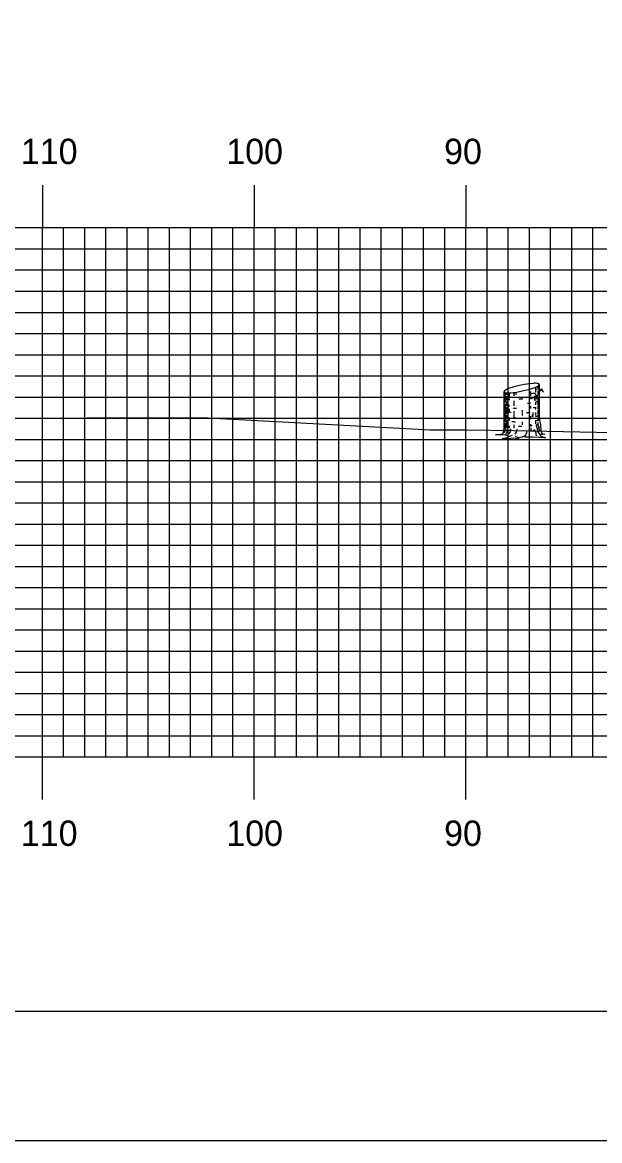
# Model space of a CAD drawing. Extents: x 1771235 to 1771579, y 442591 to 442811.
# Drawn here: x 1771290.1 to 1771317.4, y 442590.5 to 442643.4 of the extents above; entities that cross this region are included whole.
import ezdxf

# ---------------------------------------------------------------- set-up
doc = ezdxf.new("R2010")
doc.units = 0
for name, color, linetype in [('BORDER', 7, 'Continuous'), ('H_V ANNOTATION', 7, 'Continuous'), ('M_Trees_Conifer_Pay', 7, 'Continuous'), ('MAJOR', 7, 'Continuous'), ('MINOR', 7, 'Continuous'), ('PLOT BOUNDARY', 7, 'Continuous'), ('S_Roadway_Centerline', 7, 'Continuous')]:
    doc.layers.add(name, color=color, linetype=linetype)

msp = doc.modelspace()

# ---------------------------------------------------------------- linework, layer by layer
at = {"layer": 'BORDER'}
msp.add_lwpolyline([(1771251.467, 442596.665), (1771571.467, 442596.665), (1771571.467, 442806.665), (1771251.467, 442806.665)], close=True, dxfattribs=at)
at = {"layer": 'M_Trees_Conifer_Pay'}
for p, q in [((1771314.538, 442624.609), (1771314.538, 442626.256)), ((1771312.874, 442624.199), (1771312.874, 442625.921)), ((1771312.921, 442625.884), (1771312.921, 442625.412)), ((1771312.979, 442625.872), (1771312.979, 442625.775)), ((1771312.979, 442625.7), (1771312.979, 442625.496)), ((1771313.105, 442625.864), (1771313.105, 442625.632)), ((1771313.325, 442625.885), (1771313.325, 442625.717)), ((1771314.12, 442625.927), (1771314.12, 442625.727)), ((1771314.349, 442626.123), (1771314.349, 442625.9)), ((1771314.349, 442625.811), (1771314.349, 442625.764)), ((1771314.466, 442626.184), (1771314.466, 442626.021)), ((1771314.466, 442625.954), (1771314.466, 442625.826)), ((1771312.921, 442625.348), (1771312.921, 442625.04)), ((1771312.979, 442625.439), (1771312.979, 442625.239)), ((1771312.979, 442625.192), (1771312.979, 442624.856)), ((1771313.105, 442625.592), (1771313.105, 442625.517)), ((1771313.325, 442625.48), (1771313.325, 442625.243)), ((1771313.73, 442625.653), (1771313.73, 442625.558)), ((1771314.12, 442625.67), (1771314.12, 442625.581)), ((1771314.12, 442625.233), (1771314.12, 442625.128)), ((1771314.349, 442625.429), (1771314.349, 442625.297)), ((1771314.349, 442625.186), (1771314.349, 442625.076)), ((1771314.406, 442625.628), (1771314.355, 442625.569)), ((1771314.466, 442625.639), (1771314.466, 442625.303)), ((1771314.466, 442625.266), (1771314.466, 442625.103)), ((1771312.921, 442624.992), (1771312.921, 442624.5)), ((1771312.979, 442624.803), (1771312.979, 442624.667)), ((1771313.105, 442625.114), (1771313.105, 442624.975)), ((1771313.105, 442624.704), (1771313.105, 442624.562)), ((1771313.325, 442624.998), (1771313.325, 442624.846)), ((1771313.325, 442624.803), (1771313.325, 442624.63)), ((1771313.73, 442625.04), (1771313.73, 442624.966)), ((1771313.73, 442624.941), (1771313.73, 442624.792)), ((1771314.12, 442624.761), (1771314.12, 442624.615)), ((1771314.349, 442624.941), (1771314.349, 442624.799)), ((1771314.466, 442625.056), (1771314.466, 442624.84)), ((1771314.466, 442624.809), (1771314.466, 442624.735)), ((1771314.466, 442624.694), (1771314.466, 442624.521)), ((1771312.921, 442624.447), (1771312.921, 442624.199)), ((1771312.979, 442624.568), (1771312.979, 442624.189)), ((1771313.105, 442624.3), (1771313.105, 442624.206)), ((1771313.325, 442624.352), (1771313.325, 442624.199)), ((1771313.73, 442624.5), (1771313.73, 442624.347)), ((1771314.12, 442624.383), (1771314.12, 442624.294)), ((1771314.349, 442624.572), (1771314.349, 442624.399)), ((1771313.105, 442623.806), (1771313.267, 442623.87)), ((1771313.542, 442623.742), (1771313.416, 442623.806))]:
    msp.add_line(p, q, dxfattribs=at)
for points in [[(1771314.321, 442625.717), (1771314.29, 442625.632), (1771314.286, 442625.565), (1771314.317, 442625.501)], [(1771314.355, 442625.754), (1771314.391, 442625.68), (1771314.439, 442625.737), (1771314.496, 442625.805), (1771314.589, 442625.999), (1771314.653, 442626.046), (1771314.684, 442626.053)], [(1771314.369, 442625.501), (1771314.406, 442625.628), (1771314.47, 442625.744), (1771314.5, 442625.811), (1771314.569, 442625.958)], [(1771314.584, 442625.987), (1771314.659, 442625.995), (1771314.731, 442625.896)], [(1771313.053, 442625.227), (1771313.047, 442625.322), (1771313.09, 442625.299), (1771313.09, 442625.204)], [(1771314.192, 442624.828), (1771314.204, 442624.751), (1771314.252, 442624.761), (1771314.239, 442624.928)], [(1771314.538, 442624.609), (1771314.589, 442624.347), (1771314.605, 442624.074), (1771314.663, 442623.948), (1771314.799, 442623.918), (1771314.569, 442623.88), (1771314.569, 442623.88), (1771314.575, 442623.833), (1771314.822, 442623.738), (1771314.548, 442623.755), (1771314.192, 442623.775), (1771313.87, 442623.765), (1771313.877, 442623.847), (1771313.729, 442623.765), (1771313.542, 442623.742), (1771313.566, 442623.674), (1771313.298, 442623.718), (1771313.078, 442623.691), (1771312.785, 442623.708), (1771313.074, 442623.765), (1771313.105, 442623.806), (1771312.942, 442623.864), (1771312.705, 442623.874), (1771312.464, 442623.874), (1771312.806, 442623.932), (1771312.847, 442624.012), (1771312.874, 442624.199)], [(1771312.922, 442624.152), (1771312.901, 442624.074), (1771312.88, 442623.979)], [(1771313, 442624.132), (1771313.006, 442624.016), (1771312.952, 442623.927), (1771312.942, 442623.864)], [(1771313.162, 442624.158), (1771313.162, 442624.027), (1771313.074, 442623.927)], [(1771313.389, 442623.918), (1771313.456, 442624.012), (1771313.483, 442624.152)], [(1771314.128, 442624.216), (1771314.138, 442624.09), (1771314.212, 442624.047)], [(1771314.365, 442624.321), (1771314.439, 442624.216), (1771314.443, 442624.043), (1771314.569, 442623.88)], [(1771314.464, 442624.467), (1771314.47, 442624.321), (1771314.517, 442624.253), (1771314.527, 442624.053)], [(1771313.877, 442623.847), (1771313.951, 442623.989), (1771313.961, 442624.09)], [(1771314.406, 442623.827), (1771314.391, 442623.965), (1771314.317, 442624.094)]]:
    msp.add_lwpolyline(points, dxfattribs=at)
for centre, radius, start, end in [((1771314.73, 442621.153), 5.179, 101.7194, 108.0594), ((1771314.73, 442621.153), 5.179, 95.3794, 101.7194), ((1771314.319, 442625.511), 0.802, 79.2194, 95.3794), ((1771314.422, 442626.053), 0.251, 71.0501, 79.2194), ((1771314.349, 442626.406), 0.251, 304.2194, 312.3887), ((1771314.477, 442626.212), 0.0817, 56.7194, 71.0501), ((1771314.463, 442626.282), 0.0817, 312.3887, 326.7194), ((1771314.493, 442626.237), 0.0527, 46.923, 56.7194), ((1771314.508, 442626.252), 0.0314, 34.2194, 46.923), ((1771314.487, 442626.266), 0.0527, 326.7194, 336.5158), ((1771314.512, 442626.255), 0.0264, 23.4074, 34.2194), ((1771314.507, 442626.257), 0.0314, 336.5158, 349.2194), ((1771314.515, 442626.256), 0.0226, 11.7194, 23.4074), ((1771314.515, 442626.256), 0.0226, 0.0315, 11.7194), ((1771314.511, 442626.256), 0.0264, 349.2194, 0.0315), ((1771312.906, 442625.743), 0.0334, 163.9485, 180), ((1771312.906, 442625.743), 0.0334, 180, 196.0515), ((1771312.905, 442625.92), 0.0314, 156.5158, 169.2194), ((1771312.9, 442625.921), 0.0264, 169.2194, 180.0315), ((1771312.896, 442625.921), 0.0226, 180.0315, 191.7194), ((1771312.896, 442625.921), 0.0226, 191.7194, 203.4074), ((1771312.916, 442625.746), 0.0441, 196.0515, 210), ((1771312.925, 442625.911), 0.0527, 146.7194, 156.5158), ((1771312.9, 442625.922), 0.0264, 203.4074, 214.2194), ((1771312.904, 442625.925), 0.0314, 214.2194, 226.923), ((1771312.932, 442625.755), 0.0624, 210, 228.7494), ((1771312.949, 442625.895), 0.0817, 132.3887, 146.7194), ((1771312.919, 442625.94), 0.0527, 226.923, 236.7194), ((1771312.935, 442625.965), 0.0817, 236.7194, 251.0501), ((1771313.004, 442625.837), 0.172, 228.7494, 240), ((1771313.063, 442625.771), 0.251, 124.2194, 132.3887), ((1771312.989, 442626.124), 0.251, 251.0501, 259.2194), ((1771313.204, 442626.182), 0.571, 240, 240.3367), ((1771313.373, 442625.315), 0.802, 108.0594, 124.2194), ((1771313.092, 442626.666), 0.802, 259.2194, 275.3794), ((1771312.682, 442631.024), 5.179, 275.3794, 281.7194), ((1771313.706, 442629.933), 4.124, 264.6955, 266.7331), ((1771312.682, 442631.024), 5.179, 281.7194, 288.0594), ((1771313.706, 442629.933), 4.124, 276.238, 278.1032), ((1771314.207, 442626.415), 0.571, 278.1032, 284.3667), ((1771314.039, 442626.862), 0.802, 288.0594, 304.2194), ((1771314.207, 442626.57), 0.571, 284.4317, 292.4132), ((1771314.207, 442626.415), 0.571, 297.0237, 300), ((1771314.406, 442626.225), 0.172, 300, 311.2506), ((1771314.406, 442626.07), 0.172, 300, 311.2506), ((1771314.479, 442626.142), 0.0624, 311.2506, 330), ((1771314.479, 442625.988), 0.0624, 311.2506, 330), ((1771314.494, 442626.133), 0.0441, 330, 343.9485), ((1771314.494, 442625.979), 0.0441, 330, 343.9485), ((1771314.505, 442626.13), 0.0334, 343.9485, 354.2151), ((1771314.505, 442625.976), 0.0334, 343.9485, 354.2151), ((1771312.906, 442625.296), 0.0334, 163.9485, 180), ((1771312.906, 442625.296), 0.0334, 180, 196.0515), ((1771312.916, 442625.299), 0.0441, 196.0515, 210), ((1771312.932, 442625.308), 0.0624, 210, 228.7494), ((1771313.004, 442625.391), 0.172, 228.7494, 240), ((1771313.204, 442625.736), 0.571, 240, 240.3367), ((1771313.205, 442625.971), 0.571, 240, 247.0587), ((1771313.204, 442626.182), 0.571, 246.8597, 257.9846), ((1771313.705, 442629.7), 4.124, 268.0751, 270), ((1771313.705, 442629.7), 4.124, 270, 270.3581), ((1771313.706, 442629.489), 4.124, 273.7052, 275.9504), ((1771313.705, 442629.7), 4.124, 275.7849, 277.0558), ((1771313.705, 442629.253), 4.124, 277.6125, 278.1032), ((1771314.205, 442625.736), 0.571, 278.1032, 286.9296), ((1771314.207, 442625.971), 0.571, 284.4493, 297.0429), ((1771314.205, 442625.736), 0.571, 297.1896, 300), ((1771314.405, 442625.391), 0.172, 300, 311.2506), ((1771314.477, 442625.308), 0.0624, 311.2506, 330), ((1771314.493, 442625.299), 0.0441, 330, 343.9485), ((1771314.503, 442625.296), 0.0334, 343.9485, 354.2151), ((1771314.504, 442625.532), 0.0334, 343.9485, 354.2151), ((1771312.906, 442625.086), 0.0334, 163.9485, 180), ((1771312.906, 442625.086), 0.0334, 180, 196.0515), ((1771312.906, 442624.849), 0.0334, 163.9485, 180), ((1771312.906, 442624.849), 0.0334, 180, 196.0515), ((1771312.906, 442624.651), 0.0334, 163.9485, 180), ((1771312.916, 442625.089), 0.0441, 196.0515, 210), ((1771312.916, 442624.852), 0.0441, 196.0515, 210), ((1771312.932, 442625.098), 0.0624, 210, 228.7494), ((1771312.932, 442624.861), 0.0624, 210, 228.7494), ((1771313.004, 442625.181), 0.172, 228.7494, 240), ((1771313.004, 442624.944), 0.172, 228.7494, 240), ((1771313.204, 442625.526), 0.571, 240, 246.8597), ((1771313.204, 442625.289), 0.571, 240, 246.8597), ((1771313.204, 442625.526), 0.571, 259.2707, 261.8968), ((1771313.705, 442629.043), 4.124, 261.8968, 263.1474), ((1771313.705, 442629.253), 4.124, 264.081, 266.6676), ((1771313.705, 442628.806), 4.124, 264.716, 266.3193), ((1771313.705, 442629.043), 4.124, 270, 270.3581), ((1771313.705, 442629.043), 4.124, 273.1493, 275.4569), ((1771314.205, 442625.289), 0.571, 285.3983, 297.1896), ((1771314.205, 442625.526), 0.571, 297.1896, 300), ((1771314.405, 442625.181), 0.172, 300, 311.2506), ((1771314.477, 442625.098), 0.0624, 311.2506, 330), ((1771314.477, 442624.664), 0.0624, 311.2506, 330), ((1771314.493, 442625.089), 0.0441, 330, 343.9485), ((1771314.493, 442624.654), 0.0441, 330, 343.9485), ((1771314.503, 442625.086), 0.0334, 343.9485, 354.2151), ((1771314.503, 442624.651), 0.0334, 343.9485, 354.2151), ((1771312.906, 442624.456), 0.0334, 163.9485, 180), ((1771312.906, 442624.456), 0.0334, 180, 196.0515), ((1771312.906, 442624.235), 0.0334, 163.9485, 180), ((1771312.906, 442624.235), 0.0334, 180, 196.0515), ((1771312.916, 442624.459), 0.0441, 196.0515, 210), ((1771312.916, 442624.238), 0.0441, 196.0515, 210), ((1771312.932, 442624.468), 0.0624, 210, 228.7494), ((1771312.932, 442624.248), 0.0624, 210, 228.7494), ((1771313.004, 442624.551), 0.172, 228.7494, 240), ((1771313.004, 442624.33), 0.172, 228.7494, 240), ((1771313.193, 442625.097), 0.571, 241.2369, 248.0268), ((1771313.204, 442624.896), 0.571, 240, 246.8597), ((1771313.204, 442624.675), 0.571, 240, 244.5314), ((1771313.705, 442628.193), 4.124, 262.4438, 263.512), ((1771313.705, 442628.609), 4.124, 263.4991, 265.8397), ((1771313.705, 442628.413), 4.124, 267.8117, 270), ((1771313.705, 442628.413), 4.124, 270, 270.1328), ((1771313.705, 442628.413), 4.124, 275.7849, 276.7896), ((1771313.705, 442628.193), 4.124, 277.3684, 278.1032), ((1771314.205, 442624.675), 0.571, 278.1032, 281.637), ((1771314.205, 442624.896), 0.571, 288.5067, 297.2721), ((1771314.205, 442625.091), 0.571, 289.2907, 300), ((1771314.405, 442624.746), 0.172, 300, 311.2506), ((1771314.405, 442624.33), 0.172, 300, 311.2506), ((1771314.477, 442624.248), 0.0624, 311.2506, 330), ((1771314.493, 442624.238), 0.0441, 330, 343.9485), ((1771314.503, 442624.235), 0.0334, 343.9485, 354.2151)]:
    msp.add_arc(centre, radius, start, end, dxfattribs=at)
at = {"layer": 'MAJOR'}
for p, q in [((1771291.067, 442635.669), (1771291.067, 442633.665)), ((1771301.067, 442635.669), (1771301.067, 442633.665)), ((1771311.067, 442635.669), (1771311.067, 442633.665)), ((1771261.067, 442633.665), (1771541.067, 442633.665)), ((1771261.067, 442633.665), (1771541.067, 442633.665)), ((1771291.067, 442608.665), (1771291.067, 442633.665)), ((1771301.067, 442608.665), (1771301.067, 442633.665)), ((1771311.067, 442608.665), (1771311.067, 442633.665)), ((1771261.067, 442628.665), (1771541.067, 442628.665)), ((1771261.067, 442623.665), (1771541.067, 442623.665)), ((1771261.067, 442618.665), (1771541.067, 442618.665)), ((1771261.067, 442613.665), (1771541.067, 442613.665)), ((1771261.067, 442608.665), (1771541.067, 442608.665)), ((1771261.067, 442608.665), (1771541.067, 442608.665)), ((1771291.067, 442606.661), (1771291.067, 442608.665)), ((1771301.067, 442606.661), (1771301.067, 442608.665)), ((1771311.067, 442606.661), (1771311.067, 442608.665))]:
    msp.add_line(p, q, dxfattribs=at)
at = {"layer": 'MINOR'}
for p, q in [((1771292.067, 442608.665), (1771292.067, 442633.665)), ((1771293.067, 442608.665), (1771293.067, 442633.665)), ((1771294.067, 442608.665), (1771294.067, 442633.665)), ((1771295.067, 442608.665), (1771295.067, 442633.665)), ((1771296.067, 442608.665), (1771296.067, 442633.665)), ((1771297.067, 442608.665), (1771297.067, 442633.665)), ((1771298.067, 442608.665), (1771298.067, 442633.665)), ((1771299.067, 442608.665), (1771299.067, 442633.665)), ((1771300.067, 442608.665), (1771300.067, 442633.665)), ((1771302.067, 442608.665), (1771302.067, 442633.665)), ((1771303.067, 442608.665), (1771303.067, 442633.665)), ((1771304.067, 442608.665), (1771304.067, 442633.665)), ((1771305.067, 442608.665), (1771305.067, 442633.665)), ((1771306.067, 442608.665), (1771306.067, 442633.665)), ((1771307.067, 442608.665), (1771307.067, 442633.665)), ((1771308.067, 442608.665), (1771308.067, 442633.665)), ((1771309.067, 442608.665), (1771309.067, 442633.665)), ((1771310.067, 442608.665), (1771310.067, 442633.665)), ((1771312.067, 442608.665), (1771312.067, 442633.665)), ((1771313.067, 442608.665), (1771313.067, 442633.665)), ((1771314.067, 442608.665), (1771314.067, 442633.665)), ((1771315.067, 442608.665), (1771315.067, 442633.665)), ((1771316.067, 442608.665), (1771316.067, 442633.665)), ((1771317.067, 442608.665), (1771317.067, 442633.665)), ((1771261.067, 442632.665), (1771541.067, 442632.665)), ((1771261.067, 442631.665), (1771541.067, 442631.665)), ((1771261.067, 442630.665), (1771541.067, 442630.665)), ((1771261.067, 442629.665), (1771541.067, 442629.665)), ((1771261.067, 442627.665), (1771541.067, 442627.665)), ((1771261.067, 442626.665), (1771541.067, 442626.665)), ((1771261.067, 442625.665), (1771541.067, 442625.665)), ((1771261.067, 442624.665), (1771541.067, 442624.665)), ((1771261.067, 442622.665), (1771541.067, 442622.665)), ((1771261.067, 442621.665), (1771541.067, 442621.665)), ((1771261.067, 442620.665), (1771541.067, 442620.665)), ((1771261.067, 442619.665), (1771541.067, 442619.665)), ((1771261.067, 442617.665), (1771541.067, 442617.665)), ((1771261.067, 442616.665), (1771541.067, 442616.665)), ((1771261.067, 442615.665), (1771541.067, 442615.665)), ((1771261.067, 442614.665), (1771541.067, 442614.665)), ((1771261.067, 442612.665), (1771541.067, 442612.665)), ((1771261.067, 442611.665), (1771541.067, 442611.665)), ((1771261.067, 442610.665), (1771541.067, 442610.665)), ((1771261.067, 442609.665), (1771541.067, 442609.665))]:
    msp.add_line(p, q, dxfattribs=at)
at = {"layer": 'PLOT BOUNDARY'}
msp.add_lwpolyline([(1771235.281, 442590.547), (1771575.281, 442590.547), (1771575.281, 442810.547), (1771235.281, 442810.547)], close=True, dxfattribs=at)
at = {"layer": 'S_Roadway_Centerline'}
msp.add_lwpolyline([(1771261.067, 442625.671), (1771263.095, 442625.617), (1771268.422, 442625.35), (1771275.522, 442625.038), (1771285.624, 442624.666), (1771286.784, 442624.651), (1771287.698, 442624.665), (1771298.589, 442624.703), (1771309.404, 442624.118), (1771311.113, 442624.118), (1771313.33, 442624.077), (1771328.929, 442623.769), (1771334.708, 442623.416), (1771344.096, 442623.092), (1771347.049, 442623.018)], dxfattribs=at)

# ---------------------------------------------------------------- texts
at = {"layer": 'H_V ANNOTATION'}
for s, p in [('110', (1771290.051, 442636.665)), ('100', (1771299.751, 442636.665)), ('90', (1771310.04, 442636.665)), ('110', (1771290.051, 442604.465)), ('100', (1771299.751, 442604.465)), ('90', (1771310.04, 442604.465))]:
    msp.add_text(s, height=1.2, dxfattribs=at).set_placement(p)

doc.saveas('drawing.dxf')
